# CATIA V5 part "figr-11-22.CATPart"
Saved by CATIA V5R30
Part number: Part1
Bounding box of the stored display mesh (mm): x -89.703 to 75.958, y -127.286 to 108.862, z -26.487 to 19.815
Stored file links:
  D:\PROJECTS\CATIA V56R 2020\Resources\Parts File\c11_catia_v5_6r2020_prt\figr-11-22.CATPart
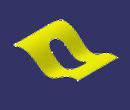
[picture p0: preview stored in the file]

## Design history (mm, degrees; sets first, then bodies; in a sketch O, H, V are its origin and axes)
Set1
  Extrude1: Element1 Sketch3, Lim1 86, Lim2 94, Direction yz-plane
  Sketch1 on xy-plane, origin (0, 0, 0), H (1, 0, 0), V (0, 1, 0)
    line L1 (64.3059, 108.8616) -> (75.9293, -106.0218)
    arc A1 centre (55.7837, -107.1115) radius 20.175 from (75.9293, -106.0218) to (55.7837, -127.2865) cw
    line L2 (55.7837, -127.2865) -> (-64.7868, -127.2865)
    arc A2 centre (-64.7868, -102.3613) radius 24.9252 from (-64.7868, -127.2865) to (-89.6873, -101.2501) cw
    line L3 (-89.6873, -101.2501) -> (-80.3115, 108.8616)
    line L4 (-80.3115, 108.8616) -> (64.3059, 108.8616)
    tangency: A1 L1, A2 L2, A2 L3, A1 L2
    horizontal: L2 H, L4 H
  Extrude2: Element1 Sketch1, Lim1 86, Lim2 94, Direction xy-plane
  Split1: ToCut Extrude1, Cutting Extrude2
  Sketch2 on xy-plane, origin (0, 0, 0), H (1, 0, 0), V (0, 1, 0)
    construction line L1 (-11.3849, 28.4134) -> (-11.3849, -36.9379)
    line L2 (12.8382, 28.4134) -> (12.8382, -36.9379)
    line L3 (-35.608, -36.9379) -> (-35.608, 28.4134)
    arc A1 centre (-11.3849, -36.9379) radius 24.2231 from (12.8382, -36.9379) to (-35.608, -36.9379) cw
    arc A2 centre (-11.3849, 28.4134) radius 24.2231 from (-35.608, 28.4134) to (12.8382, 28.4134) cw
    vertical: L1 V
    tangency: A1 L2, A2 L2, A1 L3, A2 L3
    parallelism: L1 L2
  Extrude3: Element1 Sketch2, Lim1 86, Lim2 94, Direction xy-plane
  Split2: ToCut Split1, Cutting Extrude3
  Boundary1: Boundary edge of Split2, Support Split2
Body1 (main body)
  Sketch3 on yz-plane, origin (0, 0, 0), H (0, 1, 0), V (0, 0, 1)
    spline S1 through (-130.9721, 0) (-85.5087, 19.8151) (-38.0512, 0) (0, -25.6483) (60.0541, -1.7202) (134.7951, -4.3868)
    point P1 (-130.9721, 0)
    point P2 (-38.0512, 0)
    point P3 (0, -25.6483)
    coincidence: P1 H, P2 H, P3 V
